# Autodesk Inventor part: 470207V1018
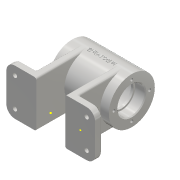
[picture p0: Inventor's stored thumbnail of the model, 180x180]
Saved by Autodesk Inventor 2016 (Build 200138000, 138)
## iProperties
Created: 2017-02
Part Number: 470207V1018
Material: 알루미늄 6061
Document SubType Name: Modeling
Designer: H
Mass: 352.777 g
Surface Area: 422.357 cm^2
Volume: 130.658 cm^3
Density: 2.7 g/cm^3
Appearance: 알루미늄 - 평지
Author: H
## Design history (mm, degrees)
sketch "스케치1"
  geometry: L1 (52, -27)-(52, 27); L2 (-52, 27)-(-52, -27); L3 (0, 0)-(0, -48.333); L4 (17, 27)-(17, -27); L5 (-17, 27)-(-17, -27); L6 (52, 27)-(17, 27); L7 (-17, 27)-(-52, 27); L8 (-52, -27)-(-17, -27); L9 (17, -27)-(52, -27)
  constraints: 18 end point, 6 perpendicular, 5 parallel, 2 horizontal, 1 vertical
  dimensions: "d0" = 104 distance between parallel lines of L2 L1; "d2" = 52 distance between parallel lines of L1 L3; "d3" = 17 distance between parallel lines of L3 L4; "d4" = 17 distance between parallel lines of L3 L5; "d5" = 54 distance between parallel lines of L8 L7; "d6" = 54 distance between parallel lines of L6 L9
extrude "돌출1" new body sketch "스케치1" distance "d7" = 8; taper "d8" = 0 deg
fillet "모깎기1" dims "d9" = 10
sketch "스케치3"
  geometry: L1 (-17, -27)-(-17, 27) reference; L2 (17, 27)-(17, -27) reference; L3 (-42, 27)-(-17, 27) reference; L4 (-25, 27)-(-25, -27); L5 (-42, -27)-(-17, -27) reference; L6 (17, 27)-(42, 27) reference; L7 (25, 27)-(25, -27); L8 (42, -27)-(17, -27) reference; 1 further point
  constraints: 4 end point, 4 point on line, 2 perpendicular
  dimensions: "d10" = 8 distance between parallel lines of L1 L4; "d11" = 8 distance between parallel lines of L2 L7
extrude "돌출2" join sketch "스케치3" distance "d12" = 52; taper "d13" = 0 deg
sketch "스케치4"
  geometry: L1 (-25, 8)-(-25, 60) reference; L2 (25, 60)-(17, 60) reference; L3 (-17, 0)-(-42, 0) reference; L4 (25, 8)-(25, 60) reference; L5 (-35, 60)-(35, 60); L6 (-35, 60)-(-35, 87); L7 (-35, 87)-(35, 87); L8 (35, 87)-(35, 60); L9 (0, 0)-(0, 139.91); L10 (0, 0)-(139.91, 0)
  constraints: 12 end point, 3 perpendicular, 2 horizontal, 1 vertical
  dimensions: "d15" = 60 distance between parallel lines of L5 L3; "d18" = 35 distance between parallel lines of L9 L6; "d19" = 70 distance between parallel lines of L8 L6; "d20" = 54 diameter of L7 L5
revolve "회전1" sketch "스케치4" stored, may be unused: angle "d21" = 90 deg
sketch "스케치5"
  geometry: 1 further point
sketch "스케치6"
  geometry: C1 r 27 at (0, 0) reference; C2 r 16 at (0, 0); 1 further point
  constraints: 1 centre point, 1 coincident
  dimensions: "d22" = 32 diameter of C2
extrude "돌출3" cut sketch "스케치6" distance "d23" = 12; taper "d24" = 0 deg
sketch "스케치7"
  geometry: C1 r 27 at (0, 0) reference; C2 r 14 at (0, 0); 1 further point
  constraints: 1 centre point, 1 coincident
  dimensions: "d25" = 28 diameter of C2
extrude "돌출4" cut sketch "스케치7" distance "d26" = 3; taper "d27" = 0 deg
sketch "스케치8"
  geometry: C1 r 27 at (0, 0) reference; C2 r 22 at (0, 0); 1 further point
  constraints: 1 centre point, 1 coincident
  dimensions: "d28" = 44 diameter of C2
extrude "돌출5" cut sketch "스케치8" distance "d29" = 40; taper "d30" = 0 deg
sketch "스케치9"
  geometry: C1 r 27 at (0, 0) reference; C2 r 16 at (0, 0); 1 further point
  constraints: 1 centre point, 1 coincident
  dimensions: "d31" = 32 diameter of C2
extrude "돌출6" cut sketch "스케치9" distance "d32" = 12; taper "d33" = 0 deg
sketch "스케치10"
  geometry: C1 r 16 at (0, 0) reference; C2 r 27 at (0, 0) reference; C3 r 14 at (0, 0); 1 further point
  constraints: 1 centre point, 1 coincident
  dimensions: "d34" = 28 diameter of C3
extrude "돌출7" cut sketch "스케치10" distance "d35" = 12; taper "d36" = 0 deg
sketch "스케치11"
  geometry: L1 (-10, 92)-(-5, 92); L2 (-5, 92)-(-5, 83.453); L3 (-5, 83.453)-(-10, 83.453); L4 (-10, 83.453)-(-10, 92); L5 (-35, 33)-(-35, 87) reference; L6 (-35, 87)-(35, 87) reference; 1 further point
  constraints: 8 end point, 2 parallel, 1 horizontal, 1 perpendicular
  dimensions: "d37" = 25 distance between parallel lines of L5 L4; "d38" = 5 distance between parallel lines of L6 L1; "d39" = 10 diameter of L2 L4
revolve "회전2" sketch "스케치11" stored, may be unused: angle "d40" = 90 deg
sketch "스케치12"
  geometry: C1 r 5 at (0, 0) reference; 1 further point
hole "구멍1" sketch "스케치12" at (0, 0) diameter "d41" = 5.188; stored, may be unused: countersink angle "d45" = 90 deg, drill point angle "d47" = 118 deg; dims "d42" = 12, "d43" = 4, "d44" = 2, "d46" = 20.25
sketch "스케치13" dims "d48" = 42
  geometry: L1 (0, 0)-(0, 31.509); C1 r 16 at (0, 0) reference; C2 r 27 at (0, 0) reference; C3 r 16 at (0, 0) reference; 2 further points
  constraints: 2 end point, 1 coincident, 1 point on line, 1 vertical, 1 vertical alignment, 2 other
hole "구멍2" sketch "스케치13" at (0, 21) diameter "d49" = 3.242; stored, may be unused: countersink angle "d53" = 90 deg, drill point angle "d55" = 118 deg; dims "d50" = 8, "d51" = 4, "d52" = 2, "d54" = 10
sketch "스케치14"
  geometry: L1 (41.007, -15.1)-(36.103, -18.284); L2 (36.103, -18.284)-(32.835, -13.252); L3 (32.835, -13.252)-(37.739, -10.068); L4 (37.739, -10.068)-(41.007, -15.1); L5 (60, 0)-(18.199, 0); C1 r 27 at (60, 0) reference; 1 further point
  constraints: 10 end point, 2 parallel, 1 horizontal, 1 perpendicular
  dimensions: "d59" = 33 deg angle of L5 L3; "d60" = 30 distance from line of L5.start L2; "d61" = 5.84691 distance between parallel lines of L2 L4; "d62" = 12 diameter of L1 L3
revolve "회전3" sketch "스케치14" stored, may be unused: angle "d63" = 90 deg
sketch "스케치15"
  geometry: C1 r 6 at (0, 0) reference; 1 further point
hole "구멍3" sketch "스케치15" at (0, 0) diameter "d64" = 5.188; stored, may be unused: countersink angle "d68" = 90 deg, drill point angle "d70" = 118 deg; dims "d65" = 12, "d66" = 4, "d67" = 2, "d69" = 16
sketch "스케치16"
  geometry: 1 further point
node "작업 평면1"
sketch "스케치17"
  geometry: L1 (-35, 87)-(35, 87) reference; L2 (-35, 33)-(-35, 87) reference; 2 further points
  constraints: 1 other
  dimensions: "d72" = 27 distance from line of L1 point (0, 60); "d73" = 35 distance from line of point (0, 60) L2
feature "엠보싱1" sketch "스케치17" dims "d74" = 0.5, "d75" = 0
sketch "스케치18"
  geometry: A1 r 10 centre (42, 17) between (52, 17) and (42, 27) reference; A2 r 10 centre (42, -17) between (42, -27) and (52, -17) reference; A3 r 10 centre (-42, -17) between (-52, -17) and (-42, -27) reference; A4 r 10 centre (-42, 17) between (-42, 27) and (-52, 17) reference; 1 further point
hole "구멍4" sketch "스케치18" at (42, 17), (42, -17), (-42, -17), (-42, 17) diameter "d76" = 5; stored, may be unused: countersink angle "d80" = 90 deg, drill point angle "d82" = 118 deg; dims "d77" = 12, "d78" = 9, "d79" = 3, "d81" = 16
sketch "스케치19"
  geometry: L1 (39.402, 12.5)-(36.804, 17); L2 (36.804, 17)-(39.402, 21.5); L3 (39.402, 21.5)-(44.598, 21.5); L4 (44.598, 21.5)-(47.196, 17); L5 (47.196, 17)-(44.598, 12.5); L6 (44.598, 12.5)-(39.402, 12.5); L7 (39.402, -21.5)-(36.804, -17); L8 (36.804, -17)-(39.402, -12.5); L9 (39.402, -12.5)-(44.598, -12.5); L10 (44.598, -12.5)-(47.196, -17); L11 (47.196, -17)-(44.598, -21.5); L12 (44.598, -21.5)-(39.402, -21.5); L13 (-44.598, -21.5)-(-47.196, -17); L14 (-47.196, -17)-(-44.598, -12.5); L15 (-44.598, -12.5)-(-39.402, -12.5); L16 (-39.402, -12.5)-(-36.804, -17); L17 (-36.804, -17)-(-39.402, -21.5); L18 (-39.402, -21.5)-(-44.598, -21.5); L19 (-44.598, 12.5)-(-47.196, 17); L20 (-47.196, 17)-(-44.598, 21.5); L21 (-44.598, 21.5)-(-39.402, 21.5); L22 (-39.402, 21.5)-(-36.804, 17); L23 (-36.804, 17)-(-39.402, 12.5); L24 (-39.402, 12.5)-(-44.598, 12.5); C1 r 2.5 at (42, -17) reference; C2 r 2.5 at (-42, -17) reference; C3 r 2.5 at (-42, 17) reference; 15 further points
  constraints: 48 end point, 5 coincident, 4 midpoint, 4 vertical alignment, 1 point on line, 56 other
extrude "돌출8" cut sketch "스케치19" distance "d83" = 3; taper "d84" = 0 deg
extrude "돌출9" cut sketch "스케치19" distance "d85" = 3; taper "d86" = 0 deg
fillet "모깎기2" dims "d87" = 2
fillet "모깎기3" dims "d88" = 2
fillet "모깎기4" dims "d89" = 2
fillet "모깎기5" dims "d90" = 3
fillet "모깎기6" dims "d91" = 0.3
chamfer "모따기1" distance "d92" = 1; stored, may be unused: second distance "d93" = 2, angle "d94" = 45 deg
chamfer "모따기2" distance "d95" = 1; stored, may be unused: second distance "d96" = 2, angle "d97" = 45 deg
fillet "모깎기7" dims "d98" = 2
node "솔리드1"
pattern_circular "원형 패턴1" dims angle "d57" = 360 deg
mirror "대칭1"
node "투영된 루프1"
node "투영된 루프2"
node "투영된 루프3"
other parameters: "d1" = 54, "d71" = 32.5
